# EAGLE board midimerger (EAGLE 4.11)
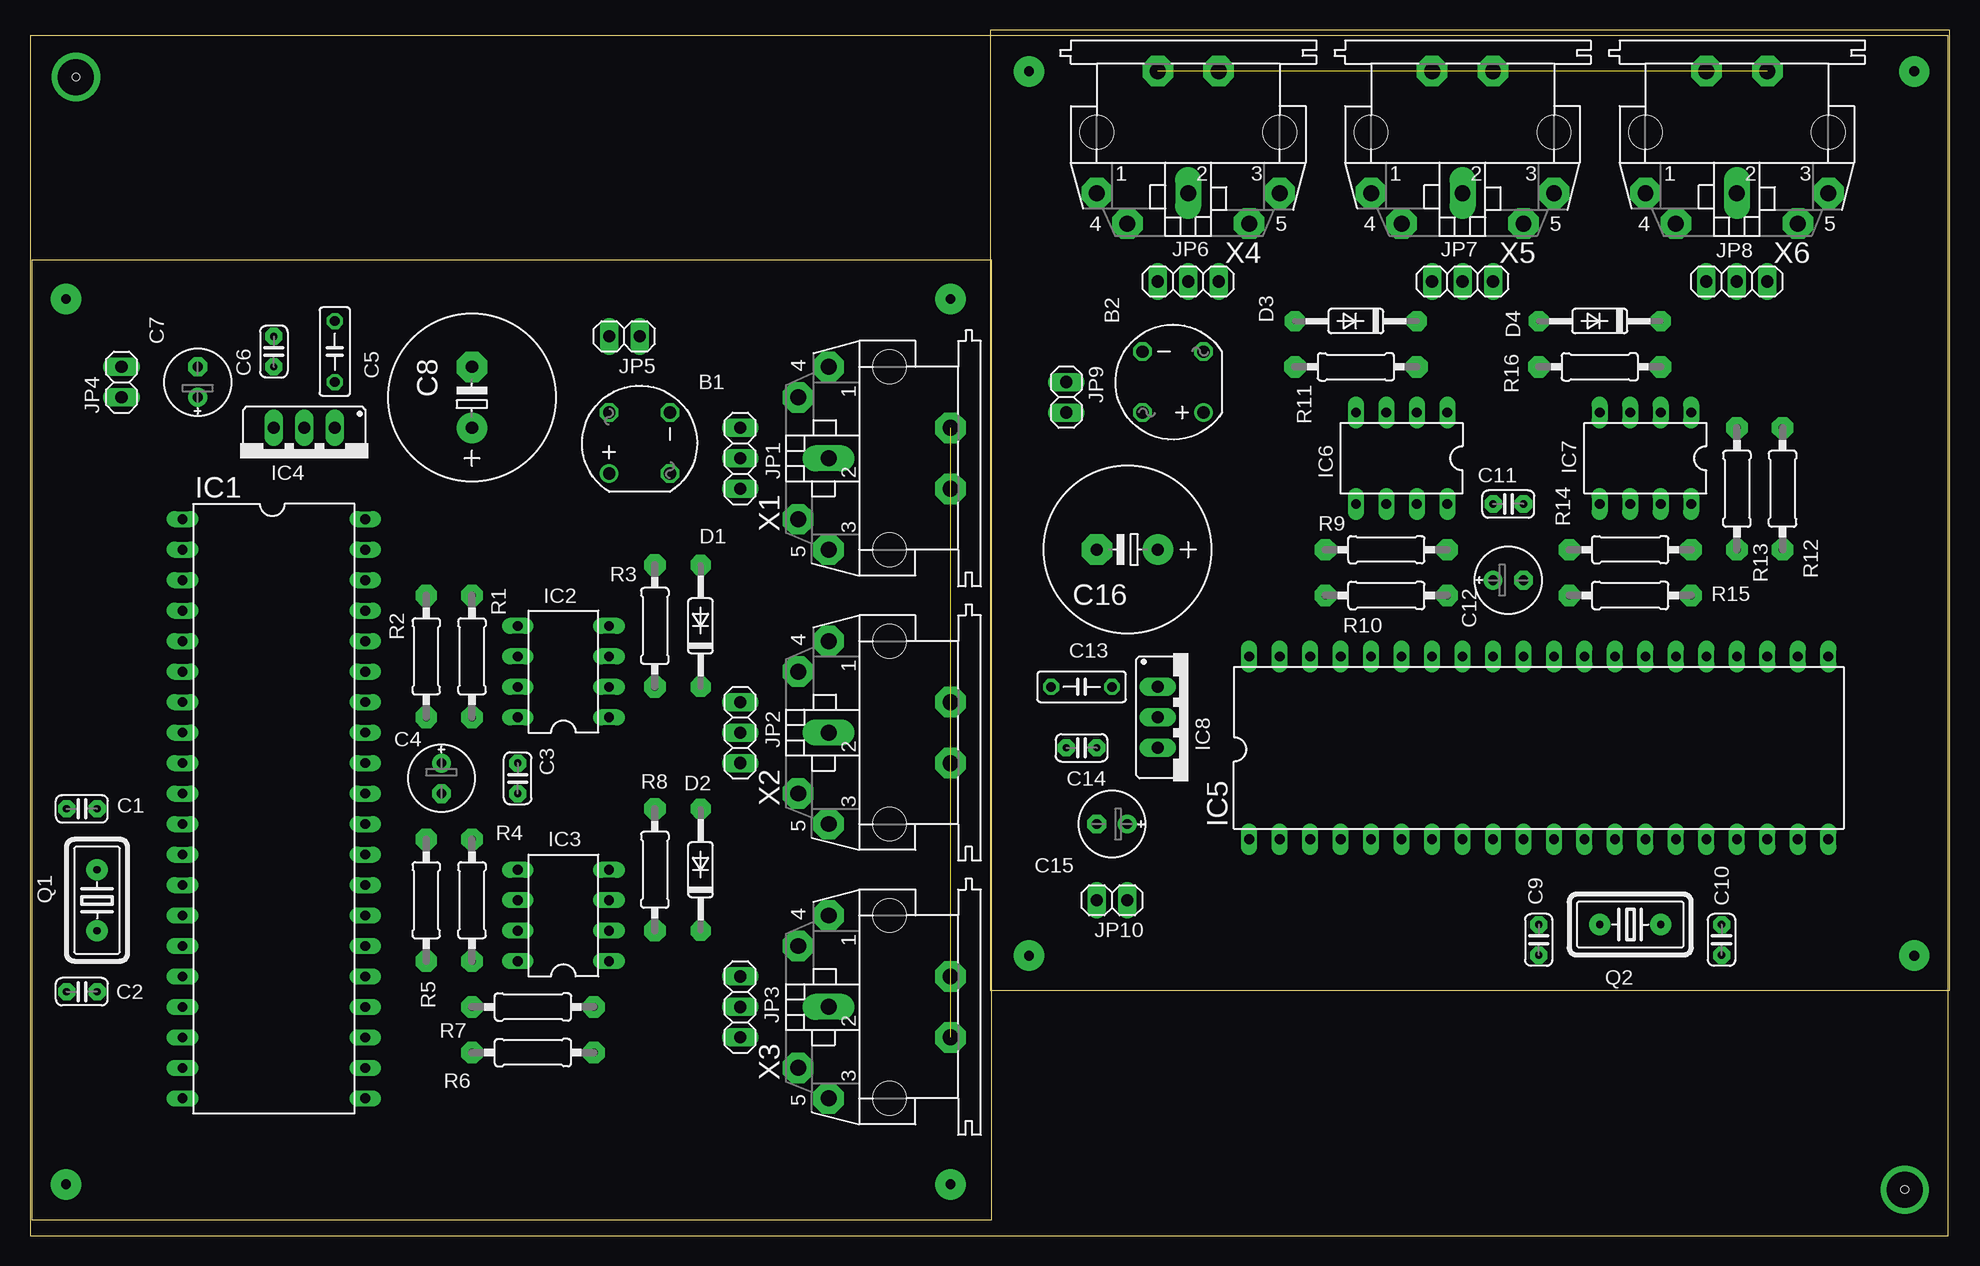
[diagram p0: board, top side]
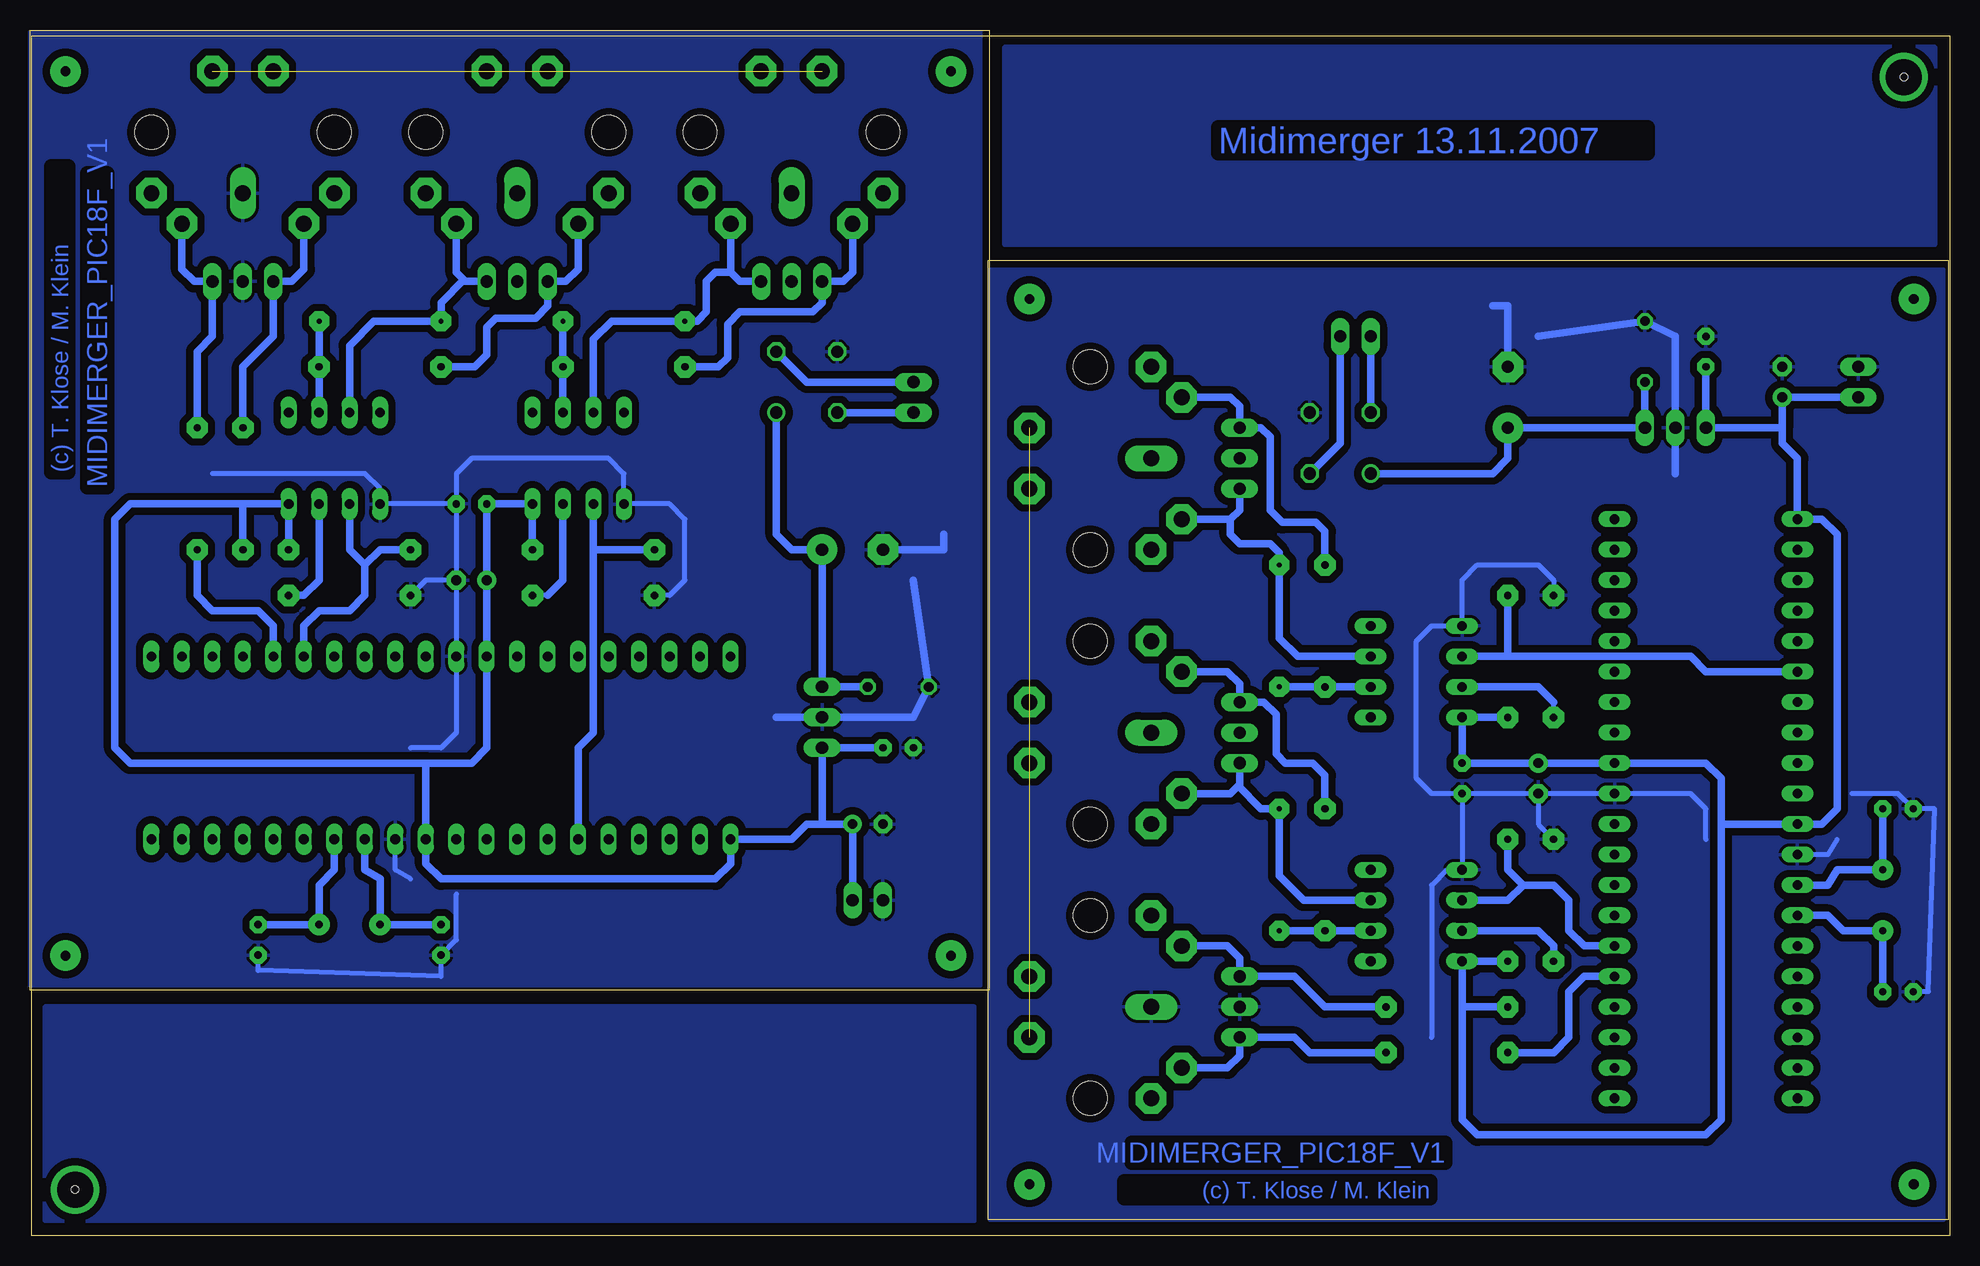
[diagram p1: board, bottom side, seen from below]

Size 159.98 x 100.46 mm. Coordinates in mm from the lower left corner, seen from the top.
Outline: 0.13,1.31 80.14,1.31 80.14,81.26 0.13,81.26 0.13,1.31
Outline: 0,0 159.85,0 159.85,99.99 0,99.99 0,0
Outline: 159.98,20.45 159.98,100.46 80.03,100.46 80.03,20.45 159.98,20.45
Copper layers (1*16): Top 0.035mm / dielectric 1.5mm / Bottom 0.035mm
Design rules "default": minimum track width 10mil, minimum drill 24mil, track to track 8mil, track to pad 8mil, pad to pad 8mil, via to via 8mil, smd to smd 8mil, copper to edge 0mil, drill to drill 8mil, minimum pad ring 10mil, minimum via ring 8mil, stop-mask expansion 4mil, vias tented up to drill 0mil, thermal gap 10mil

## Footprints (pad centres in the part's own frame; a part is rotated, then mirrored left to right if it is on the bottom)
RB1A = drill 1.016 round: + -2.54,2.54 | drill 1.016 octagon: - 2.54,-2.54; AC1 2.54,2.54; AC2 -2.54,-2.54
C025-024X044 = drill 0.61 pad 1.422 octagon: 1 -1.27,0; 2 1.27,0
E2,5-6E = drill 0.813 pad 1.575 round: + -1.27,0 | drill 0.813 pad 1.575 octagon: - 1.27,0
C050-025X075 = drill 0.813 octagon: 1 -2.54,0; 2 2.54,0
E5-13 = drill 1.016 pad 2.54 round: + -2.54,0 | drill 1.016 pad 2.54 octagon: - 2.54,0
DO35-10 = drill 0.406 pad 1.676 octagon: A 5.08,0; C -5.08,0
CNC-MARKER = drill 3 round: P$1 0,0 | hole 0.61: 0,0
DIL40 = drill 0.813 long: 1 -24.13,-7.62; 2 -21.59,-7.62; 3 -19.05,-7.62; 4 -16.51,-7.62; 5 -13.97,-7.62; 6 -11.43,-7.62; 7 -8.89,-7.62; 8 -6.35,-7.62; 9 -3.81,-7.62; 10 -1.27,-7.62; 11 1.27,-7.62; 12 3.81,-7.62; 13 6.35,-7.62; 14 8.89,-7.62; 15 11.43,-7.62; 16 13.97,-7.62; 17 16.51,-7.62; 18 19.05,-7.62; 19 21.59,-7.62; 20 24.13,-7.62; 21 24.13,7.62; 22 21.59,7.62; 23 19.05,7.62; 24 16.51,7.62; 25 13.97,7.62; 26 11.43,7.62; 27 8.89,7.62; 28 6.35,7.62; 29 3.81,7.62; 30 1.27,7.62; 31 -1.27,7.62; 32 -3.81,7.62; 33 -6.35,7.62; 34 -8.89,7.62; 35 -11.43,7.62; 36 -13.97,7.62; 37 -16.51,7.62; 38 -19.05,7.62; 39 -21.59,7.62; 40 -24.13,7.62
DIL08 = drill 0.813 long: 1 -3.81,-3.81; 2 -1.27,-3.81; 3 1.27,-3.81; 4 3.81,-3.81; 5 3.81,3.81; 6 1.27,3.81; 7 -1.27,3.81; 8 -3.81,3.81
78XXS = drill 1.016 long: GND 0,-2.54; IN -2.54,-2.54; OUT 2.54,-2.54
1X03 = drill 1.016 long: 1 -2.54,0; 2 0,0; 3 2.54,0
1X02 = drill 1.016 long: 1 -1.27,0; 2 1.27,0
HC18U-V = drill 0.61 pad 1.778 round: 1 -2.54,0; 2 2.54,0
0207/10 = drill 0.61 pad 1.778 octagon: 1 -5.08,0; 2 5.08,0
MAB5SH = drill 1.321 pad 2.54 octagon: 1 7.62,5.08; 3 -7.62,5.08; 4 5.08,7.62; 5 -5.08,7.62; PE -2.54,-5.08; PE@ 2.54,-5.08 | drill 1.321 pad 2.184 long: 2 0,5.08 | hole 2.794: 7.62,0; -7.62,0

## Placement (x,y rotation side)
B1  B40C800  [RB1A]  50.8,66.04 90 top
B2  B40C800  [RB1A]  95.25,71.12 180 top
C1  33pF  [C025-024X044]  4.32,35.56 0 top
C2  33pF  [C025-024X044]  4.32,20.32 0 top
C3  100nF  [C025-024X044]  40.64,38.1 270 top
C4  10µF  [E2,5-6E]  34.29,38.1 270 top
C5  330nF  [C050-025X075]  25.4,73.66 90 top
C6  100nF  [C025-024X044]  20.32,73.66 90 top
C7  10µF  [E2,5-6E]  13.97,71.12 90 top
C8  2200µF  [E5-13]  36.83,69.85 90 top
C9  33pF  [C025-024X044]  125.73,24.64 90 top
C10  33pF  [C025-024X044]  140.97,24.64 90 top
C11  100nF  [C025-024X044]  123.19,60.96 0 top
C12  10µF  [E2,5-6E]  123.19,54.61 0 top
C13  330nF  [C050-025X075]  87.63,45.72 180 top
C14  100nF  [C025-024X044]  87.63,40.64 180 top
C15  10µF  [E2,5-6E]  90.17,34.29 180 top
C16  2200µF  [E5-13]  91.44,57.15 180 top
D1  1N4148  [DO35-10]  55.88,50.8 90 top
D2  1N4148  [DO35-10]  55.88,30.48 90 top
D3  1N4148  [DO35-10]  110.49,76.2 180 top
D4  1N4148  [DO35-10]  130.81,76.2 180 top
E$1  [CNC-MARKER]  156.23,3.83 90 top
E$2  [CNC-MARKER]  3.83,96.54 90 top
IC1  18 F 452  [DIL40]  20.32,35.56 270 top
IC2  6N138  [DIL08]  44.45,46.99 90 top
IC3  6N138  [DIL08]  44.45,26.67 90 top
IC4  7805  [78XXS]  22.86,64.77 180 top
IC5  18 F 452  [DIL40]  125.73,40.64 0 top
IC6  6N138  [DIL08]  114.3,64.77 180 top
IC7  6N138  [DIL08]  134.62,64.77 180 top
IC8  7805  [78XXS]  96.52,43.18 270 top
JP1  [1X03]  59.18,64.77 90 top
JP2  [1X03]  59.18,41.91 90 top
JP3  [1X03]  59.18,19.05 90 top
JP4  [1X02]  7.62,71.12 90 top
JP5  [1X02]  49.53,74.93 180 top
JP6  [1X03]  96.52,79.5 180 top
JP7  [1X03]  119.38,79.5 180 top
JP8  [1X03]  142.24,79.5 180 top
JP9  [1X02]  86.36,69.85 270 top
JP10  [1X02]  90.17,27.94 180 top
Q1  10 MHz  [HC18U-V]  5.59,27.94 90 top
Q2  10 MHz  [HC18U-V]  133.35,25.91 180 top
R1  1.2k  [0207/10]  36.83,48.26 270 top
R2  5.6k  [0207/10]  33.02,48.26 270 top
R3  220  [0207/10]  52.07,50.8 90 top
R4  1.2k  [0207/10]  36.83,27.94 270 top
R5  5.6k  [0207/10]  33.02,27.94 270 top
R6  220  [0207/10]  41.91,15.24 0 top
R7  220  [0207/10]  41.91,19.05 0 top
R8  220  [0207/10]  52.07,30.48 90 top
R9  1.2k  [0207/10]  113.03,57.15 0 top
R10  5.6k  [0207/10]  113.03,53.34 0 top
R11  220  [0207/10]  110.49,72.39 180 top
R12  220  [0207/10]  146.05,62.23 90 top
R13  220  [0207/10]  142.24,62.23 90 top
R14  1.2k  [0207/10]  133.35,57.15 0 top
R15  5.6k  [0207/10]  133.35,53.34 0 top
R16  220  [0207/10]  130.81,72.39 180 top
X1  MAB5SH  [MAB5SH]  71.63,64.77 90 top
X2  MAB5SH  [MAB5SH]  71.63,41.91 90 top
X3  MAB5SH  [MAB5SH]  71.63,19.05 90 top
X4  MAB5SH  [MAB5SH]  96.52,91.95 180 top
X5  MAB5SH  [MAB5SH]  119.38,91.95 180 top
X6  MAB5SH  [MAB5SH]  142.24,91.95 180 top

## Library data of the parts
B1 B2 = rectifier
C1-C16 R1-R16 = rcl
D1-D4 = diode
E$1 E$2 = cncmarker
IC1-IC3 IC5-IC7 = ic-package
IC4 IC8 = v-reg
JP1-JP10 = pinhead
Q1 Q2 = crystal
X1-X6 = con-hirschmann

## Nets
+5V: C3.1 C4.+ C6.1 C7.+ IC1.1 IC1.11 IC1.32 IC2.8 IC3.8 IC4.OUT JP4.1 R1.2 R4.2 R7.1
+5V1: C11.1 C12.+ C14.1 C15.+ IC5.1 IC5.11 IC5.32 IC6.8 IC7.8 IC8.OUT JP10.1 R9.2 R13.1 R14.2
GND: B1.- C1.1 C2.1 C3.2 C4.- C5.2 C6.2 C7.- C8.- IC1.12 IC1.31 IC2.5 IC3.5 IC4.GND JP3.2 JP4.2 R2.1 R5.1 X3.2
GND1: B2.- C9.1 C10.1 C11.2 C12.- C13.2 C14.2 C15.- C16.- IC5.12 IC5.31 IC6.5 IC7.5 IC8.GND JP8.2 JP10.2 R10.1 R15.1 X6.2
N$1: C1.2 IC1.13 Q1.2
N$2: C2.2 IC1.14 Q1.1
N$3: IC1.26 IC3.6 R4.1
N$4: IC3.7 R5.2
N$5: D2.C IC3.2 R8.1
N$6: JP2.3 R8.2 X2.4
N$7: IC1.6 IC2.6 R1.1
N$8: IC2.7 R2.2
N$9: D1.A IC2.3 JP1.1 X1.5
N$10: D1.C IC2.2 R3.1
N$11: JP1.3 R3.2 X1.4
N$12: D2.A IC3.3 JP2.1 X2.5
N$13: C9.2 IC5.13 Q2.2
N$15: JP3.1 R6.2 X3.5
N$16: JP3.3 R7.2 X3.4
N$18: IC1.25 R6.1
N$21: C10.2 IC5.14 Q2.1
N$22: B1.+ C5.1 C8.+ IC4.IN
N$23: IC5.6 IC6.6 R9.1
N$24: B1.AC1 JP5.2
N$25: B1.AC2 JP5.1
N$26: IC6.7 R10.2
N$27: D3.C IC6.2 R11.1
N$28: IC5.26 IC7.6 R14.1
N$29: IC7.7 R15.2
N$30: D4.C IC7.2 R16.1
N$31: IC5.25 R12.1
N$32: B2.+ C13.1 C16.+ IC8.IN
N$33: B2.AC1 JP9.2
N$34: B2.AC2 JP9.1
N$39: JP8.1 R12.2 X6.5
N$40: JP6.3 R11.2 X4.4
N$41: D3.A IC6.3 JP6.1 X4.5
N$42: D4.A IC7.3 JP7.1 X5.5
N$43: JP7.3 R16.2 X5.4
N$44: JP8.3 R13.2 X6.4
PE: X1.PE X1.PE@ X2.PE X2.PE@ X3.PE X3.PE@
PE1: X4.PE X4.PE@ X5.PE X5.PE@ X6.PE X6.PE@

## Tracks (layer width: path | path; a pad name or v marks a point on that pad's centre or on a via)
+5V
  Bottom 0.61: 19.05,34.29 IC1.11 10.67,34.29 9.4,35.56 9.4,58.42 10.67,59.69 IC1.1 12.7,64.77 13.97,66.04 C7.+ | 19.05,34.29 19.05,38.1 20.32,39.37 IC1.32 C4.+ C3.1 IC2.8 R1.2 | R4.2 IC3.8 40.64,19.05 | 19.05,34.29 19.05,9.65 20.32,8.38 39.37,8.38 40.64,9.65 40.64,19.05 | C6.1 IC4.OUT 13.97,67.31 C7.+ | C7.+ JP4.1 | 40.64,19.05 R7.1
+5V1
  Bottom 0.61: 127,39.37 IC5.11 127,30.99 125.73,29.72 102.87,29.72 101.6,30.99 IC5.1 96.52,33.02 95.25,34.29 C15.+ | 127,39.37 123.19,39.37 121.92,40.64 IC5.32 C12.+ C11.1 IC6.8 R9.2 | R14.2 IC7.8 142.24,60.96 | 127,39.37 151.64,39.37 152.91,40.64 152.91,59.69 151.64,60.96 142.24,60.96 | C14.1 IC8.OUT 93.98,34.29 C15.+ | JP10.1 C15.+ | 142.24,60.96 R13.1
GND
  Bottom 0.406: C4.- C3.2 | C4.- IC1.31 21.59,36.83 20.32,35.56 20.32,33.02 | IC1.12 10.16,31.75 9.4,33.02 | R5.1 34.29,34.29 C4.- | C3.2 43.18,36.83 44.45,38.1 44.45,49.53 43.18,50.8 IC2.5 40.64,54.61 39.37,55.88 34.29,55.88 33.02,54.61 R2.1 | C3.2 IC3.5 41.91,30.48 43.18,29.21 43.18,16.51 | C2.1 1.78,20.32 1.27,35.56 C1.1 4.32,36.83 8.13,36.83
  Bottom 0.61: 34.29,74.93 C5.2 22.86,74.93 IC4.GND 22.86,63.5 | C8.- 36.83,77.47 38.1,77.47
  pour Bottom (isolate 0.61): 0.51,1.27 80.01,1.27 80.01,80.52 0.51,80.52
GND1
  Bottom 0.406: C11.2 C12.- | C12.- IC5.31 124.46,41.91 125.73,40.64 128.27,40.64 | IC5.12 129.54,30.48 128.27,29.72 | R15.1 127,54.61 C12.- | C11.2 124.46,63.5 123.19,64.77 111.76,64.77 110.49,63.5 IC6.5 106.68,60.96 105.41,59.69 105.41,54.61 106.68,53.34 R10.1 | C11.2 IC7.5 130.81,62.23 132.08,63.5 144.78,63.5 | C10.1 140.97,22.1 125.73,21.59 C9.1 124.46,24.64 124.46,28.45
  Bottom 0.61: 86.36,54.61 C13.2 86.36,43.18 IC8.GND 97.79,43.18 | C16.- 83.82,57.15 83.82,58.42
  pour Bottom (isolate 0.61): 160.02,20.83 160.02,100.33 80.77,100.33 80.77,20.83
N$1
  Bottom 0.61: IC1.13 10.16,29.21 9.4,30.48 Q1.2 C1.2
N$2
  Bottom 0.61: IC1.14 10.16,26.67 8.89,25.4 Q1.1 C2.2
N$3
  Bottom 0.61: IC1.26 30.48,24.13 31.75,25.4 31.75,27.94 33.02,29.21 35.56,29.21 | 35.56,29.21 36.83,30.48 R4.1 | IC3.6 36.83,27.94 35.56,29.21
N$4
  Bottom 0.61: R5.2 33.02,24.13 34.29,25.4 IC3.7
N$5
  Bottom 0.61: IC3.2 R8.1 D2.C
N$6
  Bottom 0.61: X2.4 60.2,46.99 59.18,45.97 JP2.3 57.15,44.45 56.13,43.43 56.13,40.13 55.37,39.37 53.09,39.37 52.07,38.35 R8.2
N$7
  Bottom 0.61: 36.83,48.26 IC2.6 | IC1.6 20.32,46.99 21.59,48.26 36.83,48.26 | 36.83,48.26 R1.1
N$8
  Bottom 0.406: R2.2 33.02,44.45
  Bottom 0.61: 33.02,44.45 34.29,45.72 IC2.7
N$9
  Bottom 0.61: 59.94,59.69 X1.5 | 59.94,59.69 59.18,60.45 JP1.1 | 59.94,59.69 59.94,58.42 59.18,57.66 56.64,57.66 55.88,56.9 D1.A 55.88,49.78 54.36,48.26 IC2.3
N$10
  Bottom 0.61: IC2.2 R3.1 D1.C
N$11
  Bottom 0.61: X1.4 59.94,69.85 59.18,69.09 JP1.3 57.4,67.31 56.64,66.55 56.64,60.45 55.63,59.44 52.83,59.44 52.07,58.67 R3.2
N$12
  Bottom 0.61: X2.5 59.94,36.83 59.31,37.47 | 59.31,37.47 59.18,37.59 JP2.1 | 59.31,37.47 57.4,35.56 D2.A 55.88,29.97 53.85,27.94 IC3.3
N$13
  Bottom 0.61: IC5.13 132.08,30.48 130.81,29.72 Q2.2 C9.2
N$14  (via drill 0.81 pad 2.54)
  other vias: 3,4.27
N$15
  Bottom 0.61: R6.2 53.34,15.24 54.61,16.51 JP3.1 | JP3.1 59.69,16.51 | X3.5 60.2,13.97 59.18,14.99 JP3.1
N$16
  Bottom 0.61: R7.2 52.07,19.05 54.61,21.59 JP3.3 | JP3.3 59.69,21.59 | X3.4 60.2,24.13 59.18,23.11 JP3.3
N$17  (via drill 0.81 pad 2.54)
  other vias: 76.7,4.27
N$18
  Bottom 0.61: IC1.25 30.48,21.59 31.75,20.32 31.75,16.51 33.02,15.24 R6.1
N$19  (via drill 0.81 pad 2.54)
  other vias: 3,78.05
N$20  (via drill 0.81 pad 2.54)
  other vias: 76.7,78.05
N$21
  Bottom 0.61: IC5.14 134.62,30.48 135.89,29.21 Q2.1 C10.2
N$22
  Bottom 0.61: C5.1 IC4.IN C8.+ 36.83,64.77 38.1,63.5 B1.+
N$23
  Bottom 0.61: 113.03,57.15 IC6.6 | IC5.6 114.3,40.64 113.03,41.91 113.03,57.15 | 113.03,57.15 R9.1
N$24
  Bottom 0.61: B1.AC1 JP5.2
N$25
  Bottom 0.61: JP5.1 50.8,66.04 B1.AC2
N$26
  Bottom 0.406: 116.84,53.34 R10.2
  Bottom 0.61: 116.84,53.34 115.57,54.61 IC6.7
N$27
  Bottom 0.61: IC6.2 R11.1 D3.C
N$28
  Bottom 0.61: IC5.26 137.16,50.8 135.89,52.07 133.35,52.07 132.08,53.34 132.08,55.88 | 132.08,55.88 130.81,57.15 R14.1 | IC7.6 133.35,57.15 132.08,55.88
N$29
  Bottom 0.61: R15.2 137.16,53.34 135.89,54.61 IC7.7
N$30
  Bottom 0.61: IC7.2 R16.1 D4.C
N$31
  Bottom 0.61: IC5.25 139.7,50.8 140.97,52.07 144.78,52.07 146.05,53.34 R12.1
N$32
  Bottom 0.61: C13.1 IC8.IN C16.+ 96.52,57.15 97.79,58.42 B2.+
N$33
  Bottom 0.61: JP9.2 B2.AC1
N$34
  Bottom 0.61: JP9.1 95.25,71.12 B2.AC2
N$35  (via drill 0.81 pad 2.54)
  other vias: 157.02,23.32
N$36  (via drill 0.81 pad 2.54)
  other vias: 157.02,97.02
N$37  (via drill 0.81 pad 2.54)
  other vias: 83.24,23.32
N$38  (via drill 0.81 pad 2.54)
  other vias: 83.24,97.02
N$39
  Bottom 0.61: R12.2 146.05,73.66 144.78,74.93 JP8.1 | JP8.1 144.78,80.01 | X6.5 147.32,80.52 146.3,79.5 JP8.1
N$40
  Bottom 0.61: X4.4 91.44,80.26 92.2,79.5 JP6.3 93.98,77.72 94.74,76.96 100.84,76.96 101.85,75.95 101.85,73.15 102.62,72.39 R11.2
N$41
  Bottom 0.61: 101.6,80.26 X4.5 | 101.6,80.26 100.84,79.5 JP6.1 | 101.6,80.26 102.87,80.26 103.63,79.5 103.63,76.96 104.39,76.2 D3.A 111.51,76.2 113.03,74.68 IC6.3
N$42
  Bottom 0.61: X5.5 124.46,80.26 123.83,79.63 | 123.83,79.63 123.7,79.5 JP7.1 | 123.83,79.63 125.73,77.72 D4.A 131.32,76.2 133.35,74.17 IC7.3
N$43
  Bottom 0.61: X5.4 114.3,80.52 115.32,79.5 JP7.3 116.84,77.47 117.86,76.45 121.16,76.45 121.92,75.69 121.92,73.41 122.94,72.39 R16.2
N$44
  Bottom 0.61: R13.2 142.24,72.39 139.7,74.93 JP8.3 | JP8.3 139.7,80.01 | X6.4 137.16,80.52 138.18,79.5 JP8.3
PE  (5 unrouted)
PE1  (5 unrouted)
S$1
  pour Bottom (isolate 0.61): 1.27,82.55 78.74,82.55 78.74,99.06 1.27,99.06
  pour Bottom (isolate 0.61): 81.28,19.05 158.75,19.05 158.75,1.27 81.28,1.27

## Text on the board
Bottom: Midimerger 13.11.2007 | (c) T. Klose / M. Klein | MIDIMERGER_PIC18F_V1 | MIDIMERGER_PIC18F_V1 | (c) T. Klose / M. Klein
